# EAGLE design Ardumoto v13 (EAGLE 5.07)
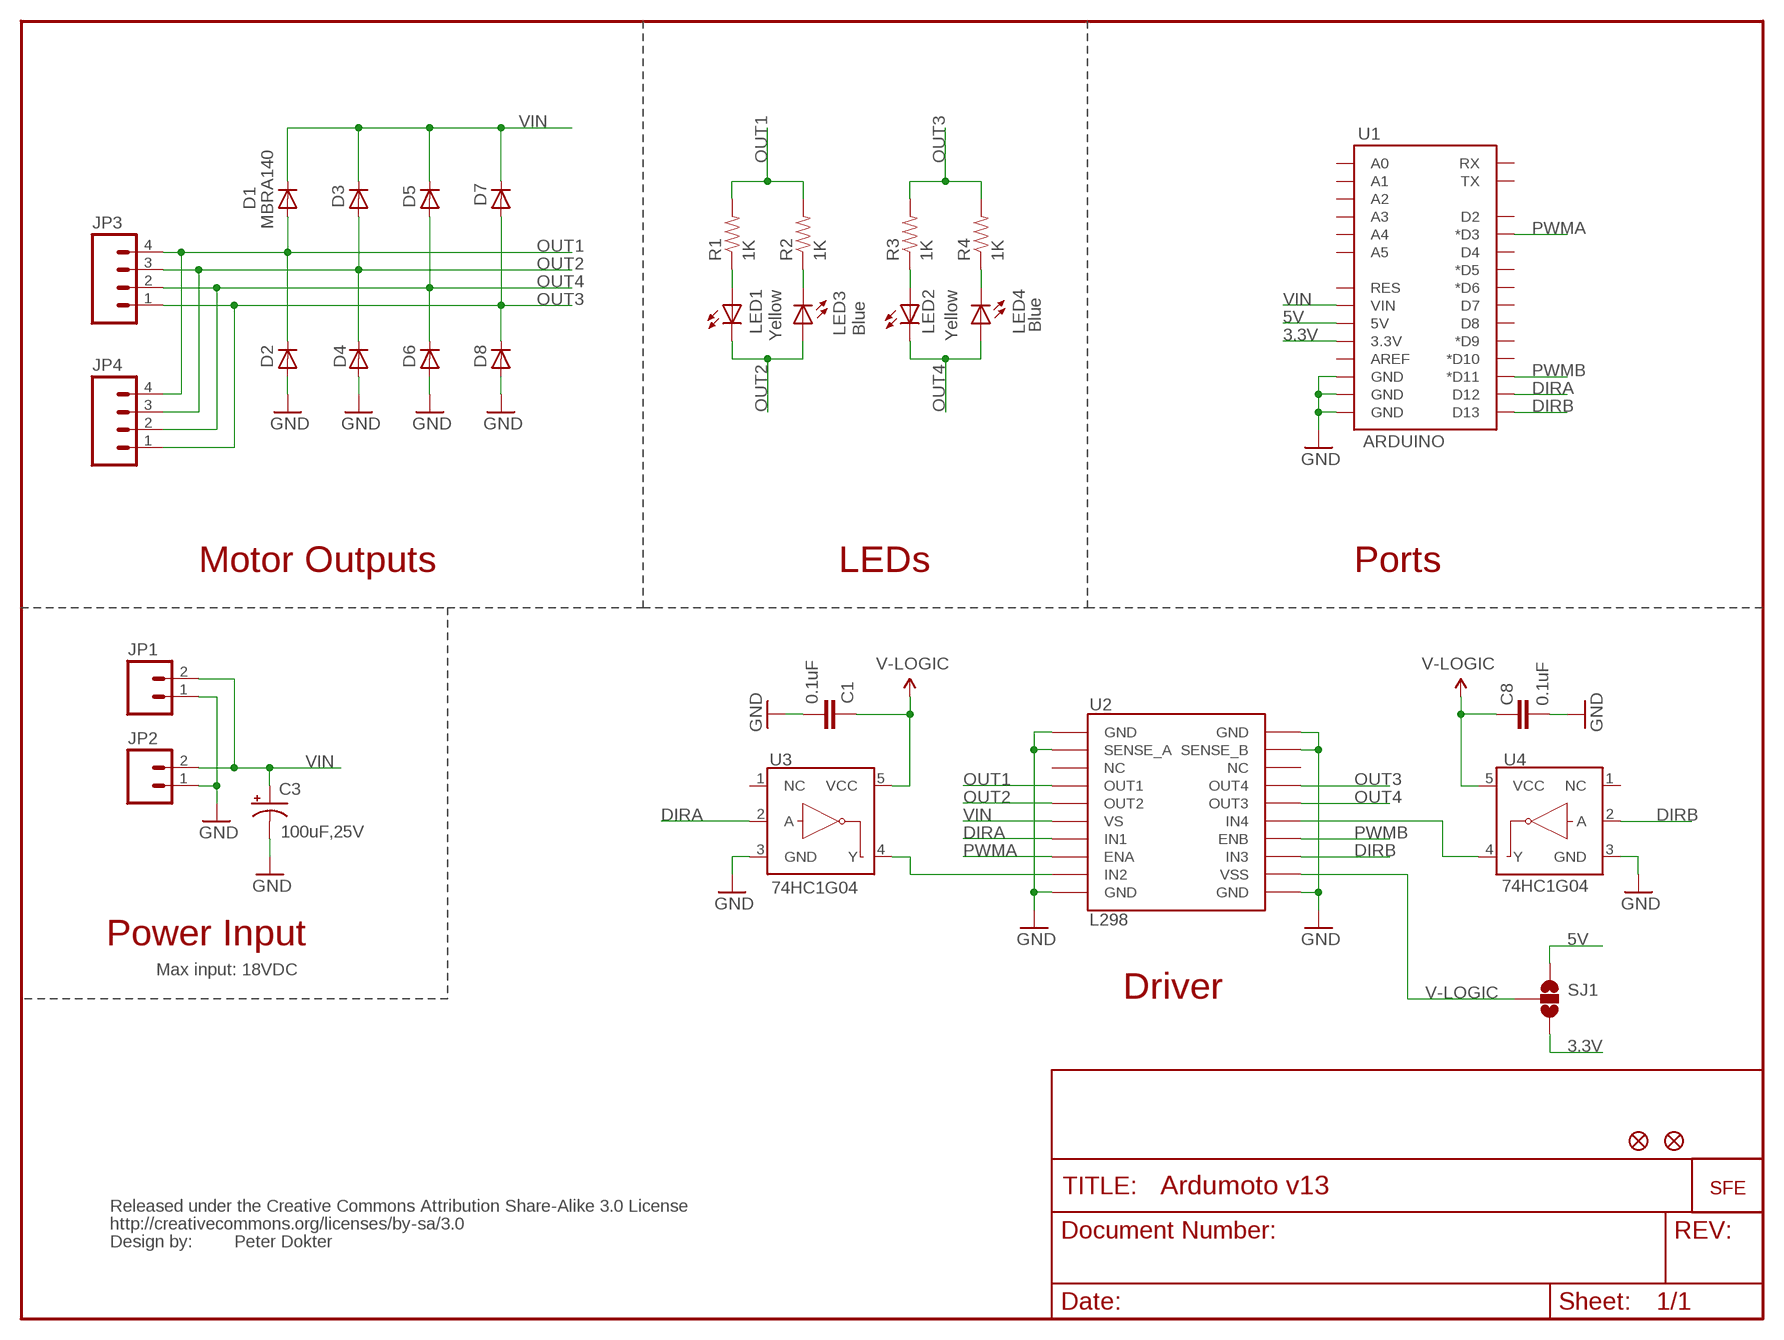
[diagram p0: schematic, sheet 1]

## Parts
C1  0.1uF  CAP0402-CAP  [0402-CAP]
C3  100uF,25V  CAP_POLF80  [NIPPON_F80]
C8  0.1uF  CAP0402-CAP  [0402-CAP]
D1  MBRA140  DIODESMA  [SMA-DIODE]
D2  MBRA140  DIODESMA  [SMA-DIODE]
D3  MBRA140  DIODESMA  [SMA-DIODE]
D4  MBRA140  DIODESMA  [SMA-DIODE]
D5  MBRA140  DIODESMA  [SMA-DIODE]
D6  MBRA140  DIODESMA  [SMA-DIODE]
D7  MBRA140  DIODESMA  [SMA-DIODE]
D8  MBRA140  DIODESMA  [SMA-DIODE]
JP1  M02PTH  [1X02]
JP2  M023.5MM  [SCREWTERMINAL-3.5MM-2]
JP3  M04SCREW  [SCREWTERMINAL-3.5MM-4]
JP4  M04PTH  [1X04]
LED1  Yellow  LED0603  [LED-0603]
LED2  Yellow  LED0603  [LED-0603]
LED3  Blue  LED0603  [LED-0603]
LED4  Blue  LED0603  [LED-0603]
R1  1K  RESISTOR0402-RES  [0402-RES]
R2  1K  RESISTOR0402-RES  [0402-RES]
R3  1K  RESISTOR0402-RES  [0402-RES]
R4  1K  RESISTOR0402-RES  [0402-RES]
SJ1  SOLDERJUMPER_2WAYPASTE1&2  [SJ_3_PASTE1&2]
U1  ARDUINO  ARDUINO_SHIELDNOLABELS  [DUEMILANOVE_SHIELD_NOLABELS]
U2  L298  L298_BRIDGE_DRIVER  [POWERSO20]
U3  74HC1G04  INVERTER""  [SC70]
U4  74HC1G04  INVERTER""  [SC70]
U$3  FIDUCIAL1X2  [FIDUCIAL-1X2]
U$4  FIDUCIAL1X2  [FIDUCIAL-1X2]
U$10  LOGO-SFENEW  [SFE-NEW-WEBLOGO]
U$11  CREATIVE_COMMONS  [CREATIVE_COMMONS]

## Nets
3.3V: SJ1.3 U1.3.3V
5V: SJ1.1 U1.5V
DIRA: U1.D12 U2.P$7(IN1) U3.2(A)
DIRB: U1.D13 U2.P$13(IN3) U4.2(A)
GND: C1.2 C3.- C8.2 D2.A D4.A D6.A D8.A JP1.1 JP2.1 U1.GND@0(GND) U1.GND@1(GND) U1.GND@2(GND) U2.P$1(GND) U2.P$2(SENSE_A) U2.P$10(GND) U2.P$11(GND) U2.P$19(SENSE_B) U2.P$20(GND) U3.3(GND) U4.3(GND)
N$1: U2.P$9(IN2) U3.4(Y)
N$2: U2.P$15(IN4) U4.4(Y)
N$4: LED1.A R1.1
N$5: LED3.C R2.1
N$8: LED2.A R3.1
N$9: LED4.C R4.1
OUT1: D1.A D2.C JP3.4 JP4.4 R1.2 R2.2 U2.P$4(OUT1)
OUT2: D3.A D4.C JP3.3 JP4.3 LED1.C LED3.A U2.P$5(OUT2)
OUT3: D7.A D8.C JP3.1 JP4.1 R3.2 R4.2 U2.P$17(OUT4)
OUT4: D5.A D6.C JP3.2 JP4.2 LED2.C LED4.A U2.P$16(OUT3)
PWMA: U1.D3(*D3) U2.P$8(ENA)
PWMB: U1.D11(*D11) U2.P$14(ENB)
V-LOGIC: C1.1 C8.1 SJ1.2 U2.P$12(VSS) U3.5(VCC) U4.5(VCC)
VIN: C3.+ D1.C D3.C D5.C D7.C JP1.2 JP2.2 U1.VIN U2.P$6(VS)
Unconnected: U1.A0 U1.A1 U1.A2 U1.A3 U1.A4 U1.A5 U1.AREF U1.D2 U1.D4 U1.D5(*D5) U1.D6(*D6) U1.D7 U1.D8 U1.D9(*D9) U1.D10(*D10) U1.RES U1.RX U1.TX U2.P$3(NC) U2.P$18(NC) U3.1(NC) U4.1(NC)

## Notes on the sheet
- Motor Outputs | LEDs | Ports
- Power Input
- Max input: 18VDC
- Driver
- Peter Dokter

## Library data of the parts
C1 C8 = SparkFun:CAP: Capacitor
C3 = SparkFun:CAP_POL: Capacitor Polarized
D1-D8 = SparkFun:DIODE: Diode
JP1 JP2 = SparkFun:M02: Header 2
JP3 JP4 = SparkFun:M04: Header 4 Standard 4-pin 0.1" header. Use with straight break away headers (SKU : PRT-00116), right angle break away headers (PRT-00553), swiss pins (PRT-00743), machine pins (PRT-00117), and female headers (PRT-00115). Molex polarized connector foot print use with SKU : PRT-08231 with associated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
LED1-LED4 = SparkFun:LED: LEDs
R1-R4 = SparkFun:RESISTOR: Resistor
SJ1 = SparkFun:SOLDERJUMPER_2WAY: Solder Jumper 2 way solder jumper
U1 = SparkFun:ARDUINO_SHIELD
U2 = SparkFun:L298_BRIDGE_DRIVER
U3 U4 = SparkFun:INVERTER: Single inverter, SOT23-5
U$3 U$4 = SparkFun:FIDUCIAL: Fiducial Alignment Points
U$10 = SparkFun:LOGO-SFE: Spark Fun Electronics PCB Logo
U$11 = SparkFun:CREATIVE_COMMONS

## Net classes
1 power: width 0.61 mm

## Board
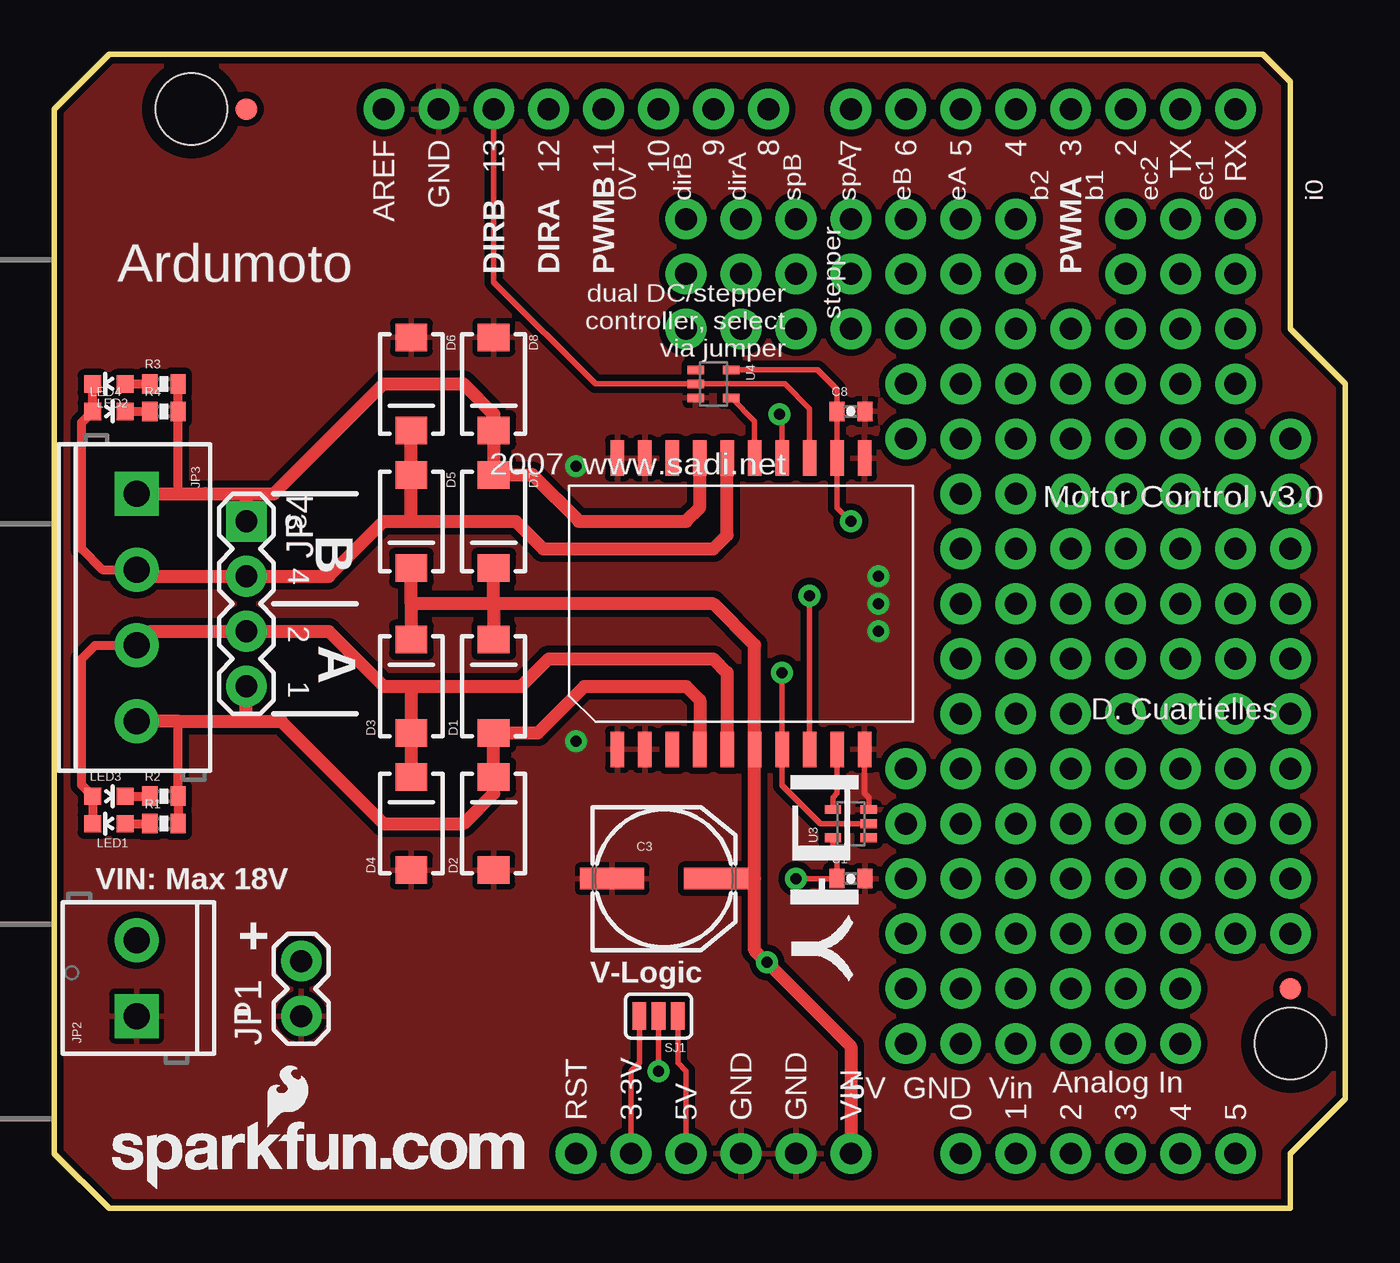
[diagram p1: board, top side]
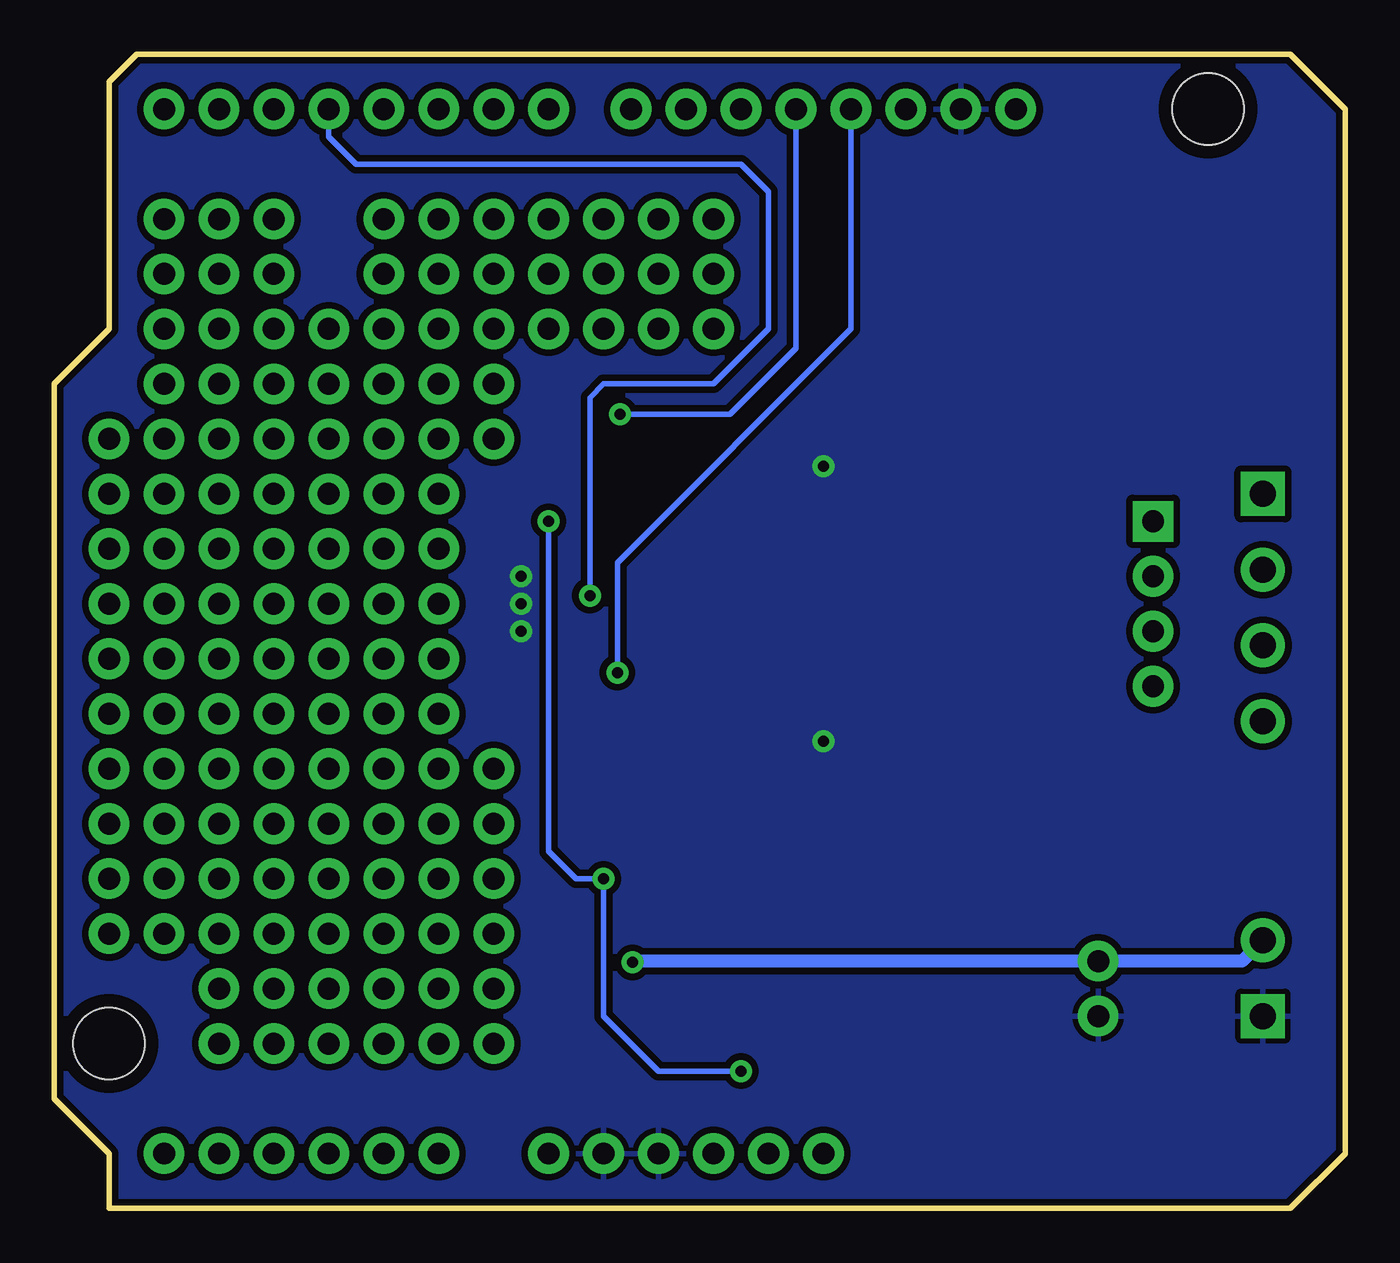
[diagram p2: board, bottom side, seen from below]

Size 59.69 x 53.34 mm. Coordinates in mm from the lower left corner, seen from the top.
Outline: 0,50.8 0,2.54 2.54,0 57.15,0 57.15,2.54 59.69,5.08 59.69,38.1 57.15,40.64 57.15,52.07 55.88,53.34 2.54,53.34 0,50.8
Copper layers (1*16): Top 0.035mm / dielectric 1.5mm / Bottom 0.035mm
Design rules "SparkFun": minimum track width 8mil, minimum drill 20mil, track to track 8mil, track to pad 8mil, pad to pad 8mil, via to via 8mil, smd to smd 8mil, copper to edge 10mil, drill to drill 8mil, minimum pad ring 12mil, minimum via ring 10mil, stop-mask expansion 4mil, vias tented up to drill 25mil, thermal gap 10mil

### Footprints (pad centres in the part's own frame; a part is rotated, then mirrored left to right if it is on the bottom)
0402-CAP = smd 0.7 x 0.9: 1 -0.65,0; 2 0.65,0
NIPPON_F80 = smd 2.95 x 1: + 2.4,0; - -2.4,0
SMA-DIODE = smd 1.27 x 1.47: A -2.15,0; C 2.15,0
1X02 = drill 1.016 pad 1.88 round: 1 0,0; 2 2.54,0
SCREWTERMINAL-3.5MM-2 = drill 1.2 pad 2.032 square: 1 0,0 | drill 1.2 pad 2.032 round: 2 3.5,0
SCREWTERMINAL-3.5MM-4 = drill 1.2 pad 2.032 square: 1 0,0 | drill 1.2 pad 2.032 round: 2 3.5,0; 3 7,0; 4 10.5,0
1X04 = drill 1.016 pad 1.88 square: 1 0,0 | drill 1.016 pad 1.88 round: 2 2.54,0; 3 5.08,0; 4 7.62,0
LED-0603 = smd 0.8 x 0.8: A 0,-0.75; C 0,0.75
0402-RES = smd 0.7 x 0.9: 1 -0.65,0; 2 0.65,0
SJ_3_PASTE1&2 = smd 0.635 x 1.27: 1 -0.889,0; 2 0,0; 3 0.889,0
DUEMILANOVE_SHIELD_NOLABELS = drill 1.016 pad 1.88 round: 3.3V 50.8,26.67; 5V 50.8,29.21; A0 50.8,41.91; A1 50.8,44.45; A2 50.8,46.99; A3 50.8,49.53; A4 50.8,52.07; A5 50.8,54.61; AREF 2.54,15.24; D2 2.54,49.53; D3 2.54,46.99; D4 2.54,44.45; D5 2.54,41.91; D6 2.54,39.37; D7 2.54,36.83; D8 2.54,33.02; D9 2.54,30.48; D10 2.54,27.94; D11 2.54,25.4; D12 2.54,22.86; D13 2.54,20.32; GND@0 50.8,31.75; GND@1 50.8,34.29; GND@2 2.54,17.78; RES 50.8,24.13; RX 2.54,54.61; TX 2.54,52.07; VIN 50.8,36.83 | hole 3.302: 45.72,57.15; 2.54,6.35
POWERSO20 = smd 1.651 x 0.635: P$1 -6.731,5.715; P$2 -6.731,4.445; P$3 -6.731,3.175; P$4 -6.731,1.905; P$5 -6.731,0.635; P$6 -6.731,-0.635; P$7 -6.731,-1.905; P$8 -6.731,-3.175; P$9 -6.731,-4.445; P$10 -6.731,-5.715; P$11 6.731,-5.715; P$12 6.731,-4.445; P$13 6.731,-3.175; P$14 6.731,-1.905; P$15 6.731,-0.635; P$16 6.731,0.635; P$17 6.731,1.905; P$18 6.731,3.175; P$19 6.731,4.445; P$20 6.731,5.715
SC70 = smd 0.4 x 0.75: 1 -0.65,-0.825; 2 0,-0.825; 3 0.65,-0.825; 4 0.65,0.825; 5 -0.65,0.825
FIDUCIAL-1X2 = smd 1 x 1: 1 0,0

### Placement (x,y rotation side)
C1  36.83,15.24 0 top
C3  28.19,15.24 0 top
C8  36.83,36.83 0 top
D1  20.32,24.13 90 top
D2  20.32,17.78 90 top
D3  16.51,24.13 90 top
D4  16.51,17.78 90 top
D5  16.51,31.75 270 top
D6  16.51,38.1 270 top
D7  20.32,31.75 270 top
D8  20.32,38.1 270 top
JP1  11.43,8.89 90 top
JP2  3.81,8.89 90 top
JP3  3.81,33.02 270 top
JP4  8.89,31.75 270 top
LED1  2.54,17.78 90 top
LED2  2.54,38.1 90 top
LED3  2.54,19.05 270 top
LED4  2.54,36.83 270 top
R1  5.08,17.78 0 top
R2  5.08,19.05 0 top
R3  5.08,38.1 0 top
R4  5.08,36.83 0 top
SJ1  27.94,8.89 180 top
U1  0,53.34 270 top
U2  31.75,27.94 90 top
U3  36.83,17.78 90 top
U4  30.48,38.1 270 top
U$3  57.15,10.16 0 top
U$4  8.89,50.8 0 top
U$10  2.67,0.89 0 top
U$11  not placed on the board

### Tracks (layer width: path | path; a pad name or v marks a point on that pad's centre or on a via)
3.3V
  Top 0.254: SJ1.3 27.05,6.73 26.67,6.35 U1.3.3V
5V
  Top 0.254: SJ1.1 28.83,6.73 29.21,6.35 U1.5V
DIRA  (via drill 0.51)
  Top 0.254: v33.66,24.77 U2.P$7 33.66,19.56 35.43,17.78 U3.2
  Bottom 0.254: v33.66,24.77 33.66,29.84 22.86,40.64 U1.D12
DIRB
  Top 0.254: U2.P$13 34.92,36.96 33.78,38.1 U4.2 25.02,38.1 20.32,42.8 U1.D13
GND  (via drill 0.51)
  Top 0.254: U2.P$10 37.47,19.18 37.66,18.99 U3.3 37.67,18.41
  other vias: 24.13,34.29 24.13,21.59 38.1,29.21 38.1,27.94 38.1,26.67
  pour Top (isolate 0.305): 0,53.34 0,0 59.69,0 59.69,53.34
  pour Bottom (isolate 0.305): 0,0 59.69,0 59.69,53.34 0,53.34
N$1
  Top 0.254: U2.P$9 36.2,19.18 36.01,18.99 U3.4
N$2
  Top 0.254: U2.P$15 32.38,36.37 U4.4
N$3  (via drill 1.02 pad 1.88)
  other vias: 54.61,38.1
N$4
  Top 0.406: LED1.A R1.1
N$5
  Top 0.406: LED3.C R2.1
N$6  (via drill 1.02 pad 1.88)
  other vias: 54.61,40.64
N$7  (via drill 1.02 pad 1.88)
  other vias: 54.61,43.18
N$8
  Top 0.406: LED2.A R3.1
N$9
  Top 0.406: LED4.C R4.1
N$10  (via drill 1.02 pad 1.88)
  other vias: 54.61,45.72
N$131  (via drill 1.02 pad 1.88)
  other vias: 54.61,12.7
N$157  (via drill 1.02 pad 1.88)
  other vias: 54.61,15.24
N$183  (via drill 1.02 pad 1.88)
  other vias: 54.61,17.78
N$209  (via drill 1.02 pad 1.88)
  other vias: 54.61,20.32
N$235  (via drill 1.02 pad 1.88)
  other vias: 54.61,22.86
N$261  (via drill 1.02 pad 1.88)
  other vias: 54.61,25.4
N$287  (via drill 1.02 pad 1.88)
  other vias: 54.61,27.94
N$313  (via drill 1.02 pad 1.88)
  other vias: 54.61,30.48
N$339  (via drill 1.02 pad 1.88)
  other vias: 41.91,17.78
N$340  (via drill 1.02 pad 1.88)
  other vias: 41.91,20.32
N$341  (via drill 1.02 pad 1.88)
  other vias: 41.91,22.86
N$342  (via drill 1.02 pad 1.88)
  other vias: 41.91,25.4
N$343  (via drill 1.02 pad 1.88)
  other vias: 41.91,27.94
N$344  (via drill 1.02 pad 1.88)
  other vias: 41.91,30.48
N$345  (via drill 1.02 pad 1.88)
  other vias: 41.91,33.02
N$346  (via drill 1.02 pad 1.88)
  other vias: 41.91,35.56
N$347  (via drill 1.02 pad 1.88)
  other vias: 41.91,38.1
N$348  (via drill 1.02 pad 1.88)
  other vias: 41.91,40.64
N$349  (via drill 1.02 pad 1.88)
  other vias: 41.91,43.18
N$350  (via drill 1.02 pad 1.88)
  other vias: 41.91,45.72
N$351  (via drill 1.02 pad 1.88)
  other vias: 41.91,7.62
N$352  (via drill 1.02 pad 1.88)
  other vias: 41.91,10.16
N$353  (via drill 1.02 pad 1.88)
  other vias: 41.91,12.7
N$354  (via drill 1.02 pad 1.88)
  other vias: 41.91,15.24
N$355  (via drill 1.02 pad 1.88)
  other vias: 39.37,7.62
N$365  (via drill 1.02 pad 1.88)
  other vias: 44.45,17.78
N$366  (via drill 1.02 pad 1.88)
  other vias: 44.45,20.32
N$367  (via drill 1.02 pad 1.88)
  other vias: 44.45,22.86
N$368  (via drill 1.02 pad 1.88)
  other vias: 44.45,25.4
N$369  (via drill 1.02 pad 1.88)
  other vias: 44.45,27.94
N$370  (via drill 1.02 pad 1.88)
  other vias: 44.45,30.48
N$371  (via drill 1.02 pad 1.88)
  other vias: 44.45,33.02
N$372  (via drill 1.02 pad 1.88)
  other vias: 44.45,35.56
N$373  (via drill 1.02 pad 1.88)
  other vias: 44.45,38.1
N$374  (via drill 1.02 pad 1.88)
  other vias: 44.45,40.64
N$375  (via drill 1.02 pad 1.88)
  other vias: 44.45,43.18
N$376  (via drill 1.02 pad 1.88)
  other vias: 44.45,45.72
N$377  (via drill 1.02 pad 1.88)
  other vias: 44.45,7.62
N$378  (via drill 1.02 pad 1.88)
  other vias: 44.45,10.16
N$379  (via drill 1.02 pad 1.88)
  other vias: 44.45,12.7
N$380  (via drill 1.02 pad 1.88)
  other vias: 44.45,15.24
N$381  (via drill 1.02 pad 1.88)
  other vias: 39.37,10.16
N$391  (via drill 1.02 pad 1.88)
  other vias: 46.99,17.78
N$392  (via drill 1.02 pad 1.88)
  other vias: 46.99,20.32
N$393  (via drill 1.02 pad 1.88)
  other vias: 46.99,22.86
N$394  (via drill 1.02 pad 1.88)
  other vias: 46.99,25.4
N$395  (via drill 1.02 pad 1.88)
  other vias: 46.99,27.94
N$396  (via drill 1.02 pad 1.88)
  other vias: 46.99,30.48
N$397  (via drill 1.02 pad 1.88)
  other vias: 46.99,33.02
N$398  (via drill 1.02 pad 1.88)
  other vias: 46.99,35.56
N$399  (via drill 1.02 pad 1.88)
  other vias: 46.99,38.1
N$400  (via drill 1.02 pad 1.88)
  other vias: 46.99,40.64
N$403  (via drill 1.02 pad 1.88)
  other vias: 46.99,7.62
N$404  (via drill 1.02 pad 1.88)
  other vias: 46.99,10.16
N$405  (via drill 1.02 pad 1.88)
  other vias: 46.99,12.7
N$406  (via drill 1.02 pad 1.88)
  other vias: 46.99,15.24
N$407  (via drill 1.02 pad 1.88)
  other vias: 39.37,12.7
N$417  (via drill 1.02 pad 1.88)
  other vias: 49.53,17.78
N$418  (via drill 1.02 pad 1.88)
  other vias: 49.53,20.32
N$419  (via drill 1.02 pad 1.88)
  other vias: 49.53,22.86
N$420  (via drill 1.02 pad 1.88)
  other vias: 49.53,25.4
N$421  (via drill 1.02 pad 1.88)
  other vias: 49.53,27.94
N$422  (via drill 1.02 pad 1.88)
  other vias: 49.53,30.48
N$423  (via drill 1.02 pad 1.88)
  other vias: 49.53,33.02
N$424  (via drill 1.02 pad 1.88)
  other vias: 49.53,35.56
N$425  (via drill 1.02 pad 1.88)
  other vias: 49.53,38.1
N$426  (via drill 1.02 pad 1.88)
  other vias: 49.53,40.64
N$427  (via drill 1.02 pad 1.88)
  other vias: 49.53,43.18
N$428  (via drill 1.02 pad 1.88)
  other vias: 49.53,45.72
N$429  (via drill 1.02 pad 1.88)
  other vias: 49.53,7.62
N$430  (via drill 1.02 pad 1.88)
  other vias: 49.53,10.16
N$431  (via drill 1.02 pad 1.88)
  other vias: 49.53,12.7
N$432  (via drill 1.02 pad 1.88)
  other vias: 49.53,15.24
N$433  (via drill 1.02 pad 1.88)
  other vias: 39.37,15.24
N$443  (via drill 1.02 pad 1.88)
  other vias: 52.07,17.78
N$444  (via drill 1.02 pad 1.88)
  other vias: 52.07,20.32
N$445  (via drill 1.02 pad 1.88)
  other vias: 52.07,22.86
N$446  (via drill 1.02 pad 1.88)
  other vias: 52.07,25.4
N$447  (via drill 1.02 pad 1.88)
  other vias: 52.07,27.94
N$448  (via drill 1.02 pad 1.88)
  other vias: 52.07,30.48
N$449  (via drill 1.02 pad 1.88)
  other vias: 52.07,33.02
N$450  (via drill 1.02 pad 1.88)
  other vias: 52.07,35.56
N$451  (via drill 1.02 pad 1.88)
  other vias: 52.07,38.1
N$452  (via drill 1.02 pad 1.88)
  other vias: 52.07,40.64
N$453  (via drill 1.02 pad 1.88)
  other vias: 52.07,43.18
N$454  (via drill 1.02 pad 1.88)
  other vias: 52.07,45.72
N$455  (via drill 1.02 pad 1.88)
  other vias: 52.07,7.62
N$456  (via drill 1.02 pad 1.88)
  other vias: 52.07,10.16
N$457  (via drill 1.02 pad 1.88)
  other vias: 52.07,12.7
N$458  (via drill 1.02 pad 1.88)
  other vias: 52.07,15.24
N$459  (via drill 1.02 pad 1.88)
  other vias: 39.37,17.78
N$460  (via drill 1.02 pad 1.88)
  other vias: 39.37,35.56
N$477  (via drill 1.02 pad 1.88)
  other vias: 31.75,40.64
N$478  (via drill 1.02 pad 1.88)
  other vias: 36.83,43.18
N$479  (via drill 1.02 pad 1.88)
  other vias: 29.21,43.18
N$480  (via drill 1.02 pad 1.88)
  other vias: 36.83,45.72
N$485  (via drill 1.02 pad 1.88)
  other vias: 39.37,20.32
N$486  (via drill 1.02 pad 1.88)
  other vias: 39.37,38.1
N$503  (via drill 1.02 pad 1.88)
  other vias: 29.21,40.64
N$504  (via drill 1.02 pad 1.88)
  other vias: 34.29,40.64
N$505  (via drill 1.02 pad 1.88)
  other vias: 31.75,43.18
N$506  (via drill 1.02 pad 1.88)
  other vias: 34.29,45.72
N$511  (via drill 1.02 pad 1.88)
  other vias: 54.61,33.02
N$512  (via drill 1.02 pad 1.88)
  other vias: 39.37,40.64
N$530  (via drill 1.02 pad 1.88)
  other vias: 36.83,40.64
N$531  (via drill 1.02 pad 1.88)
  other vias: 34.29,43.18
N$532  (via drill 1.02 pad 1.88)
  other vias: 31.75,45.72
N$537  (via drill 1.02 pad 1.88)
  other vias: 54.61,35.56
N$538  (via drill 1.02 pad 1.88)
  other vias: 39.37,43.18
N$547  (via drill 1.02 pad 1.88)
  other vias: 57.15,17.78
N$548  (via drill 1.02 pad 1.88)
  other vias: 57.15,20.32
N$549  (via drill 1.02 pad 1.88)
  other vias: 57.15,22.86
N$550  (via drill 1.02 pad 1.88)
  other vias: 57.15,25.4
N$551  (via drill 1.02 pad 1.88)
  other vias: 57.15,27.94
N$552  (via drill 1.02 pad 1.88)
  other vias: 57.15,30.48
N$553  (via drill 1.02 pad 1.88)
  other vias: 57.15,33.02
N$554  (via drill 1.02 pad 1.88)
  other vias: 57.15,35.56
N$557  (via drill 1.02 pad 1.88)
  other vias: 29.21,45.72
N$561  (via drill 1.02 pad 1.88)
  other vias: 57.15,12.7
N$562  (via drill 1.02 pad 1.88)
  other vias: 57.15,15.24
N$564  (via drill 1.02 pad 1.88)
  other vias: 39.37,45.72
OUT1
  Top 0.406: R1.2 R2.2 5.73,22.5 5.71,22.52
  Top 0.61: D1.A | D1.A D2.C 20.32,19.18 18.92,17.78 15.24,17.78 10.5,22.52 8.89,22.52 | JP3.4 5.71,22.52 8.89,22.52 | 8.89,22.52 JP4.4 | D1.A 22.36,21.98 24.51,24.13 29.21,24.13 29.84,23.5 U2.P$4
OUT2
  Top 0.406: LED1.C LED3.A 1.27,19.57 1.27,25.4 1.89,26.02 JP3.3
  Top 0.61: D4.C D3.A 16.51,24.13 | JP3.3 4.46,26.67 JP4.3 12.7,26.67 15.24,24.13 16.51,24.13 | 16.51,24.13 21.59,24.13 22.86,25.4 30.48,25.4 31.11,24.77 U2.P$5
OUT3
  Top 0.406: 7.11,33.02 7,33.13 | R3.2 R4.2 5.73,33.13 5.84,33.02
  Top 0.61: JP3.1 5.84,33.02 7.11,33.02 8.89,33.02 | 8.89,33.02 10.16,33.02 15.24,38.1 18.92,38.1 20.32,36.7 D8.C D7.A 22.1,33.91 24.26,31.75 29.21,31.75 29.84,32.38 U2.P$17 | 8.89,33.02 JP4.1
OUT4
  Top 0.406: LED2.C LED4.A 1.27,36.31 1.27,30.48 2.23,29.52 JP3.2
  Top 0.61: D6.C D5.A 16.51,31.75 | JP3.2 4.12,29.21 JP4.2 12.7,29.21 15.24,31.75 16.51,31.75 | 16.51,31.75 21.34,31.75 22.61,30.48 30.48,30.48 31.11,31.11 U2.P$16
PWMA  (via drill 0.51)
  Top 0.254: U2.P$8 v34.92,28.32
  Bottom 0.254: v34.92,28.32 34.92,37.47 34.29,38.1 29.21,38.1 26.67,40.64 26.67,46.99 27.94,48.26 45.72,48.26 46.99,49.53 U1.D3
PWMB  (via drill 0.51)
  Top 0.254: U2.P$14 33.66,36.58 v33.53,36.7
  Bottom 0.254: v33.53,36.7 28.45,36.7 25.4,39.75 U1.D11
V-LOGIC  (via drill 0.51)
  Top 0.254: U3.5 36.01,16.57 36.18,16.4 C1.1 v34.29,15.24 | v27.94,6.35 SJ1.2 | U4.5 35.29,38.75 36.18,37.86 C8.1 36.2,36.81 U2.P$12 36.2,32.38 v36.83,31.75
  Bottom 0.254: v36.83,31.75 36.83,16.51 35.56,15.24 v34.29,15.24 34.29,8.89 31.75,6.35 v27.94,6.35
VIN  (via drill 0.51)
  Top 0.61: 16.51,27.94 D3.C | 16.51,27.94 D5.C | 32.38,15.24 32.38,11.94 v32.96,11.37 36.83,7.49 U1.VIN | 32.38,15.24 U2.P$6 32.38,26.04 30.48,27.94 20.32,27.94 | 32.38,15.24 C3.+ | 20.32,27.94 D7.C | 20.32,27.94 16.51,27.94 | 20.32,27.94 D1.C
  Bottom 0.61: v32.96,11.37 32.89,11.43 JP1.2 4.77,11.43 JP2.2

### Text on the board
tPlace: AREF | GND | 13 | 12 | 11 | 10 | 9 | 8 | 7 | 6 | 5 | 4 | 3 | 2 | TX | RX | Ardumoto | DIRB | DIRA | PWMB | PWMA | 3 | B | 4 | 2 | A | 1 | VIN: Max 18V | + | V-Logic | - | Analog In | RST | 3.3V | 5V | GND | GND | VIN | 0 | 1 | 2 | 3 | 4 | 5
tNames: 0V | dirB | dirA | spB | spA | eB | eA | b2 | b1 | ec2 | ec1 | i0 | dual DC/stepper | controller, select | stepper | via jumper | 2007 www.sadi.net | Motor Control v3.0 | D. Cuartielles | 5V GND Vin
tValues: L298P013TR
